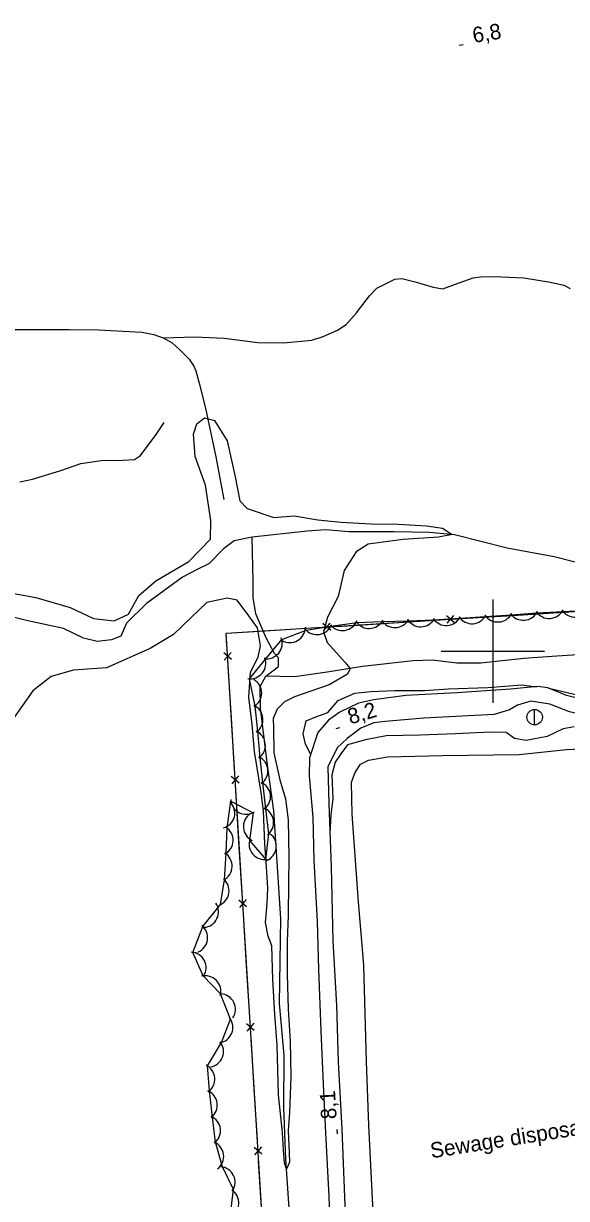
# Model space of a CAD drawing. Extents: x 643342 to 646936, y 5873857 to 5876103.
# Drawn here: x 645909.1 to 646014.3, y 5874894 to 5875121.6 of the extents above; entities that cross this region are included whole.
import ezdxf

# ---------------------------------------------------------------- set-up
doc = ezdxf.new("R2010")
doc.units = 0
for name, color, linetype in [('Niveau 2', 7, 'Continuous'), ('Niveau 21', 7, 'Continuous'), ('Niveau 22', 7, 'Continuous'), ('Niveau 3', 7, 'Continuous'), ('Niveau 33', 7, 'Continuous'), ('Niveau 36', 7, 'Continuous'), ('Niveau 37', 7, 'Continuous'), ('Niveau 4', 7, 'Continuous'), ('Niveau 44', 7, 'Continuous'), ('Niveau 61', 7, 'Continuous')]:
    doc.layers.add(name, color=color, linetype=linetype)

msp = doc.modelspace()

# ---------------------------------------------------------------- linework, layer by layer
at = {"layer": 'Niveau 2'}
for points in [[(645903.7, 5875011.81), (645911.48, 5875010.41), (645918.12, 5875008.48), (645922.65, 5875006.32), (645926.69, 5875005.91), (645929.41, 5875007.16), (645931.46, 5875010.81), (645934.72, 5875013.63), (645941.16, 5875017.39), (645945.35, 5875021.71), (645945.36, 5875025.33), (645944.37, 5875032.15), (645942.37, 5875037.74), (645942.04, 5875042.03), (645942.71, 5875044.06), (645944.19, 5875045.22), (645946.1, 5875044.71), (645948.57, 5875040.73), (645950.09, 5875033.77), (645951.03, 5875029.16), (645952.43, 5875027.62), (645957.58, 5875025.88), (645961.53, 5875026.2), (645966.14, 5875025.47), (645970.61, 5875025.02), (645976.42, 5875024.66), (645981.67, 5875024.61), (645987.18, 5875024.28), (645990.25, 5875023.85), (645992.13, 5875022.59), (645989.48, 5875022.12), (645982.63, 5875021.65), (645975.87, 5875020.72), (645973.53, 5875019.27), (645971.24, 5875015.61), (645970.05, 5875010.63), (645968.02, 5875006.57), (645967.24, 5875003.78)], [(645958.5, 5874914.05), (645958.23, 5874923.67), (645957.78, 5874929.6), (645957.38, 5874936.41), (645957.23, 5874942.95), (645956.5, 5874944.82), (645955.95, 5874947.41), (645956.31, 5874951.12), (645956.43, 5874954.11), (645956.18, 5874958.24), (645955.84, 5874962.71), (645955.58, 5874969.06), (645955.14, 5874972.6), (645953.83, 5874980.57), (645953.37, 5874985.79), (645952.73, 5874991.12), (645953.06, 5874995.93), (645954.59, 5874998.84), (645955.01, 5875001.03), (645954.45, 5875004.5), (645952.76, 5875006.83), (645950.48, 5875009.89), (645948.58, 5875010.28), (645944.62, 5875009.43), (645941.57, 5875006.53), (645938.19, 5875003.26), (645933.66, 5875000.53), (645925.18, 5874996.79), (645918.79, 5874996.35), (645914.44, 5874995.12), (645910.91, 5874992.3), (645906.9, 5874986.65)], [(645967.24, 5875003.78), (645967.92, 5875001.72), (645969.14, 5875000.35), (645971.43, 5874997.82), (645972.4, 5874996.65), (645971.85, 5874995.56), (645968.32, 5874993.51), (645961.61, 5874991.18), (645959.64, 5874990.22), (645958.23, 5874988.78), (645957.49, 5874986.98), (645957.52, 5874985.17), (645957.59, 5874980.33), (645958.75, 5874975.09), (645959.86, 5874971.37), (645960.4, 5874967.32), (645960.49, 5874960.03), (645960.46, 5874955), (645960.35, 5874948.86), (645960.15, 5874943.76), (645960.18, 5874937.34), (645960.34, 5874930.63), (645960.75, 5874924.46), (645960.87, 5874917.58), (645960.64, 5874910.61), (645960.38, 5874907.14), (645960.57, 5874902.8), (645960.62, 5874901.02), (645960.07, 5874899.67), (645959.68, 5874900.9), (645959.47, 5874903.28), (645959.29, 5874906.77), (645958.5, 5874914.05)], [(645964.74, 5874980.05), (645964.73, 5874980.09), (645963.71, 5874982), (645963.27, 5874984.01), (645963.89, 5874986.5), (645965.7, 5874987.27), (645968.08, 5874988.13), (645970.06, 5874990.43), (645973.27, 5874991.87), (645976.4, 5874992.2), (645981.04, 5874992.41), (645986.76, 5874992.39), (645991.39, 5874992.71), (645999.07, 5874992.95), (646005.67, 5874993.46), (646008.5, 5874993.13)], [(646010.84, 5874992.86), (646018.25, 5874991.12), (646023.69, 5874990.91), (646028.56, 5874991.19), (646031.72, 5874991.64), (646032.73, 5874991.51)], [(646015.78, 5874985.36), (646013.66, 5874984.98), (646010.57, 5874983.48), (646006.49, 5874982.68), (646004.19, 5874983.1), (646002.59, 5874984.22), (645999.55, 5874984.3), (645992.82, 5874984.01), (645985.96, 5874983.71), (645979.33, 5874983.6), (645975.36, 5874982.86), (645971.88, 5874981.87), (645970.56, 5874980.14), (645969.46, 5874978.49), (645968.83, 5874976.06), (645969.01, 5874971.41), (645968.61, 5874968.29), (645968.47, 5874964.7)]]:
    msp.add_lwpolyline(points, dxfattribs=at)
at = {"layer": 'Niveau 21'}
for points in [[(646018.8, 5874990.34), (646014.29, 5874991.43), (646010.68, 5874992.93), (646008.68, 5874993.14), (646003.47, 5874992.67), (645993.04, 5874991.95), (645983.18, 5874991.39), (645976.95, 5874990.61), (645973.97, 5874989.94), (645970.37, 5874988.17), (645968.16, 5874986.62), (645966.12, 5874984.27), (645964.52, 5874979.37), (645964.43, 5874975.87), (645965.16, 5874967.87), (645965.34, 5874959.49), (645966.01, 5874947.63), (645966.25, 5874938.43), (645966.7, 5874926.45), (645967.14, 5874916.09), (645967.62, 5874906.68), (645968.22, 5874894.35), (645968.86, 5874878.28)], [(646058.61, 5874887.28), (646058.42, 5874903.33), (646058.27, 5874915.89), (646057.71, 5874929.23), (646057.56, 5874941.79), (646057.25, 5874956.42), (646056.72, 5874969.41), (646056.22, 5874981.94), (646055.07, 5874990.93), (646054.16, 5874992.14), (646052.93, 5874992.99), (646051.07, 5874993.09), (646047.52, 5874992.38), (646043.29, 5874991.39), (646040.42, 5874990.85), (646037.79, 5874990.2), (646028.26, 5874988.5), (646024.21, 5874988.22), (646016.9, 5874987.83), (646014.88, 5874988.27), (646011.04, 5874989.76), (646007.4, 5874990.3)], [(646007.4, 5874990.3), (646004.78, 5874989.54), (646003.22, 5874988.62), (646000.26, 5874987.71), (645986.68, 5874987.01), (645979.16, 5874986.38), (645976.96, 5874986.11), (645974.47, 5874985.12), (645971.83, 5874983.07), (645969.87, 5874981.31), (645968.06, 5874977.57), (645968.25, 5874970.46), (645968.72, 5874958.25), (645969, 5874943.92), (645969.72, 5874931.37), (645970.09, 5874920.43), (645970.74, 5874907.4), (645971.28, 5874894.25), (645971.92, 5874879.71)]]:
    msp.add_lwpolyline(points, dxfattribs=at)
at = {"layer": 'Niveau 22'}
for points in [[(645936.15, 5875060.72), (645942.28, 5875060.9), (645947.96, 5875060.65), (645954.48, 5875059.79), (645959.45, 5875059.77), (645964.96, 5875060.28), (645967.14, 5875060.97), (645969.95, 5875062.2), (645971.6, 5875063.33), (645973.63, 5875065.56), (645976.15, 5875068.82), (645977.57, 5875070.31), (645979.34, 5875071.26), (645981.01, 5875072.09), (645982.36, 5875072.22), (645984.96, 5875071.58), (645988.47, 5875070.54), (645990.35, 5875070.23), (645992.61, 5875071.03), (645996.19, 5875072.33), (645997.63, 5875072.56), (646000.36, 5875072.62), (646006.03, 5875072.37), (646011.18, 5875071.48), (646013.77, 5875070.94), (646015, 5875070.28)], [(645905.33, 5875062.3), (645910.4, 5875062.33), (645917.95, 5875062.35), (645923.62, 5875062.24), (645932.05, 5875061.81), (645934.33, 5875061.34), (645936.15, 5875060.72), (645937.9, 5875059.72), (645939.33, 5875058.44), (645941.17, 5875056.56), (645942.12, 5875055.23), (645942.5, 5875054.29), (645943.11, 5875051.96), (645944.35, 5875047.06), (645946.39, 5875037.69), (645947.94, 5875029.4)], [(645908.36, 5875032.83), (645910.85, 5875033.35), (645916.35, 5875035.03), (645920.23, 5875036.37), (645924.17, 5875036.93), (645928.36, 5875037.03), (645930.59, 5875037.13), (645931.78, 5875037.93), (645934.81, 5875042.01), (645936.36, 5875044.3)]]:
    msp.add_lwpolyline(points, dxfattribs=at)
at = {"layer": 'Niveau 3'}
for p, q in [((645993.47, 5875117.44), (645994.26, 5875117.57)), ((645969.64, 5874985.02), (645970.41, 5874985.24)), ((645969.9, 5874906.52), (645969.85, 5874907.32))]:
    msp.add_line(p, q, dxfattribs=at)
at = {"layer": 'Niveau 33'}
msp.add_lwpolyline([(645976.82, 5874891.29), (645976, 5874908.17), (645975.52, 5874920.51), (645975.03, 5874939.16), (645973.97, 5874951.46), (645972.79, 5874968.43), (645972.67, 5874974.6), (645973.34, 5874976.52), (645974.38, 5874978.11), (645975.96, 5874978.92), (645979.64, 5874979.52), (645990.24, 5874979.78), (646005.15, 5874980), (646014.29, 5874980.98), (646035.9, 5874982)], dxfattribs=at)
at = {"layer": 'Niveau 36'}
msp.add_lwpolyline([(646008.12, 5874985.72), (646008.12, 5874988.72)], dxfattribs=at)
msp.add_circle((646008.12, 5874987.22), 1.5, dxfattribs=at)
at = {"layer": 'Niveau 37'}
for points in [[(646152.66, 5875016.23), (646179.19, 5874807.95), (645961.38, 5874791.81), (645948.36, 5875003.47), (646152.66, 5875016.23)], [(645967.21, 5875003.94), (645968.53, 5875005.44)], [(645969.86, 5875004.82), (645979.84, 5875005.44)], [(645979.84, 5875005.44), (645989.83, 5875006.06)], [(645992.57, 5875005.53), (645991.07, 5875006.85)], [(645991.16, 5875005.44), (645992.48, 5875006.94)], [(645993.82, 5875006.31), (646003.8, 5875006.94)], [(646003.8, 5875006.94), (646013.78, 5875007.56)], [(645948.51, 5875001.02), (645948.36, 5875003.47), (645955.89, 5875003.94)], [(645955.89, 5875003.94), (645965.87, 5875004.57)], [(645968.62, 5875004.03), (645967.12, 5875005.35)], [(645949.39, 5874998.37), (645947.89, 5874999.69)], [(645949.3, 5874999.78), (645947.97, 5874998.28)], [(645949.37, 5874987.05), (645948.76, 5874997.03)], [(645949.99, 5874977.07), (645949.37, 5874987.05)], [(645950.77, 5874975.83), (645949.45, 5874974.32)], [(645950.86, 5874974.41), (645949.36, 5874975.74)], [(645950.84, 5874963.1), (645950.23, 5874973.08)], [(645951.46, 5874953.12), (645950.84, 5874963.1)], [(645952.33, 5874950.46), (645950.83, 5874951.78)], [(645952.24, 5874951.87), (645950.92, 5874950.37)], [(645952.32, 5874939.14), (645951.7, 5874949.13)], [(645952.93, 5874929.16), (645952.32, 5874939.14)], [(645953.8, 5874926.5), (645952.3, 5874927.83)], [(645953.72, 5874927.92), (645952.39, 5874926.42)], [(645953.79, 5874915.19), (645953.18, 5874925.17)], [(645954.4, 5874905.21), (645953.79, 5874915.19)], [(645955.28, 5874902.55), (645953.78, 5874903.88)], [(645955.19, 5874903.96), (645953.86, 5874902.46)], [(645955.26, 5874891.24), (645954.65, 5874901.22)]]:
    msp.add_lwpolyline(points, dxfattribs=at)
at = {"layer": 'Niveau 4'}
for points in [[(646019.29, 5875016.44), (646011.92, 5875018.27), (646002.8, 5875019.98), (645992.57, 5875022.54), (645987.75, 5875023.03), (645980.86, 5875023.14), (645972.1, 5875023.12), (645967.63, 5875023.52), (645964.03, 5875023.27), (645953.37, 5875022.07), (645949.92, 5875021.37), (645947.82, 5875019.82), (645945, 5875016.94), (645942.74, 5875015.85), (645939.93, 5875014.37), (645937.94, 5875012.95), (645932.96, 5875009.22), (645929.04, 5875005.44), (645927.94, 5875002.91), (645926.13, 5875002.2), (645923.34, 5875001.89), (645920.72, 5875002.53), (645916.84, 5875004.37), (645909.94, 5875005.88), (645894.91, 5875009.65)], [(645960.84, 5874888.3), (645959.94, 5874901.56), (645959.52, 5874911.58), (645959.57, 5874921.75), (645958.69, 5874931.75), (645958.95, 5874948.13), (645958.23, 5874959.18), (645957.59, 5874969.07), (645956.29, 5874978.44), (645955.01, 5874988.99), (645954.93, 5874993.19), (645956.06, 5874995.14), (645958.49, 5874997.06), (645958.48, 5874998.69), (645957.71, 5874999.57), (645956.07, 5875002.73), (645954.08, 5875007.27), (645953.61, 5875010.39), (645953.61, 5875013.43), (645953.37, 5875022.07)], [(646026.87, 5874998.96), (646019.48, 5874999.5), (646012.4, 5874999.02), (646006.02, 5874998.58), (645997.69, 5874997.66), (645993.02, 5874997.68), (645988.3, 5874998.29), (645984.58, 5874998.15), (645974.75, 5874997.01), (645967.94, 5874995.96), (645961.58, 5874995.05), (645956.06, 5874995.14)]]:
    msp.add_lwpolyline(points, dxfattribs=at)
at = {"layer": 'Niveau 44'}
for points in [[(645955.44, 5874974.56), (645954.97, 5874979.39), (645954.47, 5874984.51), (645954, 5874989.35), (645952.86, 5874994.67), (645956.04, 5874998.53), (645959.12, 5875002.28), (645963.84, 5875004.08), (645968.63, 5875004.85), (645973.69, 5875005.57), (645978.54, 5875005.73), (645983.68, 5875005.9), (645988.53, 5875006.06), (645993.68, 5875006.39), (645998.52, 5875006.72), (646003.65, 5875007.07), (646008.5, 5875007.41), (646013.63, 5875007.71), (646018.48, 5875007.96)], [(645949.12, 5874890.43), (645949.75, 5874895.71), (645947.64, 5874900.08), (645946.32, 5874904.9), (645945.71, 5874909.71), (645945.11, 5874914.81), (645944.74, 5874919.65), (645947.43, 5874924.2), (645949.2, 5874928.72), (645947.29, 5874933.6), (645943.9, 5874937.08), (645941.93, 5874941.66), (645943.87, 5874946.64), (645947.27, 5874950.91), (645948.05, 5874955.7), (645948.37, 5874960.86), (645948.56, 5874965.71), (645949.28, 5874970.97), (645953.57, 5874968.7), (645952.88, 5874963.36), (645956.02, 5874959.65), (645956.61, 5874964.64), (645956.02, 5874969.46), (645955.44, 5874974.56)]]:
    msp.add_lwpolyline(points, dxfattribs=at)
for centre, start, end in [((646005.95, 5875009), 213.9515, 333.9295), ((646005.95, 5875009), 213.9515, 333.9295), ((646005.95, 5875009), 213.9515, 333.9295), ((646010.94, 5875009.34), 213.9515, 333.9295), ((646010.94, 5875009.34), 213.9515, 333.9295), ((646010.94, 5875009.34), 213.9515, 333.9295), ((646015.96, 5875009.6), 212.8764, 332.8543), ((646015.96, 5875009.6), 212.8764, 332.8543), ((646015.96, 5875009.6), 212.8764, 332.8543), ((645970.89, 5875007), 219.2125, 339.1904), ((645970.89, 5875007), 219.2125, 339.1904), ((645970.89, 5875007), 219.2125, 339.1904), ((645976.05, 5875007.41), 211.9197, 331.8977), ((645976.05, 5875007.41), 211.9197, 331.8977), ((645976.05, 5875007.41), 211.9197, 331.8977), ((645981.05, 5875007.58), 211.9197, 331.8977), ((645981.05, 5875007.58), 211.9197, 331.8977), ((645981.05, 5875007.58), 211.9197, 331.8977), ((645986.05, 5875007.74), 211.9197, 331.8977), ((645986.05, 5875007.74), 211.9197, 331.8977), ((645986.05, 5875007.74), 211.9197, 331.8977), ((645990.99, 5875007.97), 213.9515, 333.9295), ((645990.99, 5875007.97), 213.9515, 333.9295), ((645990.99, 5875007.97), 213.9515, 333.9295), ((645995.98, 5875008.31), 213.9515, 333.9295), ((645995.98, 5875008.31), 213.9515, 333.9295), ((645995.98, 5875008.31), 213.9515, 333.9295), ((646000.97, 5875008.66), 213.9515, 333.9295), ((646000.97, 5875008.66), 213.9515, 333.9295), ((646000.97, 5875008.66), 213.9515, 333.9295), ((645960.7, 5875004.67), 240.0802, 0.0582), ((645960.7, 5875004.67), 240.0802, 0.0582), ((645960.7, 5875004.67), 240.0802, 0.0582), ((645965.95, 5875006.21), 219.2125, 339.1904), ((645965.95, 5875006.21), 219.2125, 339.1904), ((645965.95, 5875006.21), 219.2125, 339.1904), ((645956.22, 5875001.53), 260.5624, 20.5404), ((645956.22, 5875001.53), 260.5624, 20.5404), ((645956.22, 5875001.53), 260.5624, 20.5404), ((645953.04, 5874997.66), 260.5624, 20.5404), ((645953.04, 5874997.66), 260.5624, 20.5404), ((645953.04, 5874997.66), 260.5624, 20.5404), ((645952.24, 5874991.88), 300.6387, 60.6166), ((645952.24, 5874991.88), 300.6387, 60.6166), ((645952.24, 5874991.88), 300.6387, 60.6166), ((645952.48, 5874986.76), 305.5995, 65.5775), ((645952.48, 5874986.76), 305.5995, 65.5775), ((645952.48, 5874986.76), 305.5995, 65.5775), ((645952.96, 5874981.78), 305.5995, 65.5775), ((645952.96, 5874981.78), 305.5995, 65.5775), ((645952.96, 5874981.78), 305.5995, 65.5775), ((645953.45, 5874976.81), 305.5995, 65.5775), ((645953.45, 5874976.81), 305.5995, 65.5775), ((645953.45, 5874976.81), 305.5995, 65.5775), ((645953.95, 5874971.79), 307.0197, 66.9977), ((645953.95, 5874971.79), 307.0197, 66.9977), ((645953.95, 5874971.79), 307.0197, 66.9977), ((645952.25, 5874971.4), 182.0663, 302.0442), ((645952.25, 5874971.4), 182.0663, 302.0442), ((645952.25, 5874971.4), 182.0663, 302.0442), ((645947.04, 5874968.65), 285.9226, 45.9005), ((645947.04, 5874968.65), 285.9226, 45.9005), ((645947.04, 5874968.65), 285.9226, 45.9005), ((645954.56, 5874966.83), 307.0197, 66.9977), ((645954.56, 5874966.83), 307.0197, 66.9977), ((645954.56, 5874966.83), 307.0197, 66.9977), ((645954.69, 5874966.03), 124.3894, 244.3673), ((645954.69, 5874966.03), 124.3894, 244.3673), ((645954.69, 5874966.03), 124.3894, 244.3673), ((645946.71, 5874963.36), 297.7831, 57.761), ((645946.71, 5874963.36), 297.7831, 57.761), ((645946.71, 5874963.36), 297.7831, 57.761), ((645955.07, 5874962.23), 293.0723, 53.0502), ((645955.07, 5874962.23), 293.0723, 53.0502), ((645955.07, 5874962.23), 293.0723, 53.0502), ((645955.8, 5874962.64), 160.2271, 280.205), ((645955.8, 5874962.64), 160.2271, 280.205), ((645955.8, 5874962.64), 160.2271, 280.205), ((645946.51, 5874958.36), 297.7831, 57.761), ((645946.51, 5874958.36), 297.7831, 57.761), ((645946.51, 5874958.36), 297.7831, 57.761), ((645945.92, 5874953.59), 290.8038, 50.7817), ((645945.92, 5874953.59), 290.8038, 50.7817), ((645945.92, 5874953.59), 290.8038, 50.7817), ((645943.88, 5874949.5), 274.2002, 34.1782), ((645943.88, 5874949.5), 274.2002, 34.1782), ((645943.88, 5874949.5), 274.2002, 34.1782), ((645941.77, 5874944.5), 291.571, 51.5489), ((645941.77, 5874944.5), 291.571, 51.5489), ((645941.77, 5874944.5), 291.571, 51.5489), ((645941.47, 5874938.69), 327.3005, 87.2784), ((645941.47, 5874938.69), 327.3005, 87.2784), ((645941.47, 5874938.69), 327.3005, 87.2784), ((645944.33, 5874934.11), 344.1898, 104.1678), ((645944.33, 5874934.11), 344.1898, 104.1678), ((645944.33, 5874934.11), 344.1898, 104.1678), ((645947.16, 5874930.62), 326.5648, 86.5428), ((645947.16, 5874930.62), 326.5648, 86.5428), ((645947.16, 5874930.62), 326.5648, 86.5428), ((645946.67, 5874927.11), 278.6205, 38.5984), ((645946.67, 5874927.11), 278.6205, 38.5984), ((645946.67, 5874927.11), 278.6205, 38.5984), ((645944.85, 5874922.45), 278.6205, 38.5984), ((645944.85, 5874922.45), 278.6205, 38.5984), ((645944.85, 5874922.45), 278.6205, 38.5984), ((645943.17, 5874917.1), 304.3866, 64.3646), ((645943.17, 5874917.1), 304.3866, 64.3646), ((645943.17, 5874917.1), 304.3866, 64.3646), ((645943.65, 5874912.05), 307.1345, 67.1124), ((645943.65, 5874912.05), 307.1345, 67.1124), ((645943.65, 5874912.05), 307.1345, 67.1124), ((645944.27, 5874907.09), 307.1345, 67.1124), ((645944.27, 5874907.09), 307.1345, 67.1124), ((645944.27, 5874907.09), 307.1345, 67.1124), ((645944.88, 5874902.13), 307.1345, 67.1124), ((645944.88, 5874902.13), 307.1345, 67.1124), ((645944.88, 5874902.13), 307.1345, 67.1124), ((645947.1, 5874897.13), 325.7678, 85.7458), ((645947.1, 5874897.13), 325.7678, 85.7458), ((645947.1, 5874897.13), 325.7678, 85.7458), ((645947.83, 5874893.09), 297.2628, 57.2408), ((645947.83, 5874893.09), 297.2628, 57.2408), ((645947.83, 5874893.09), 297.2628, 57.2408)]:
    msp.add_arc(centre, 3, start, end, dxfattribs=at)
at = {"layer": 'Niveau 61'}
for points in [[(646000, 5875010), (646000, 5875000), (646000, 5874990)], [(645990, 5875000), (646000, 5875000), (646010, 5875000)]]:
    msp.add_lwpolyline(points, dxfattribs=at)

# ---------------------------------------------------------------- texts
at = {"layer": 'Niveau 3'}
for s, rotation, p in [('6,8  ', 8.9405, (645996.32, 5875117.85)), ('8,2  ', 16.4364, (645972.41, 5874985.79)), ('8,1  ', 93.3312, (645969.77, 5874909.4))]:
    msp.add_text(s, height=3, rotation=rotation, dxfattribs=at).set_placement(p)
at = {"layer": 'Niveau 33'}
msp.add_text('Sewage disposal pond', height=3, rotation=8.9405, dxfattribs=at).set_placement((645988.14, 5874901.75))

doc.saveas('drawing.dxf')
